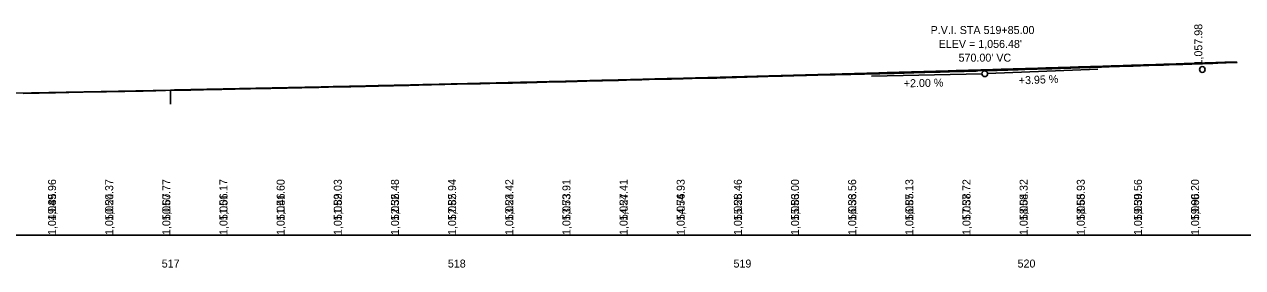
# Model space of a CAD drawing. Extents: x 2241514 to 2245530, y 509521 to 510188.
# Drawn here: x 2241926.1 to 2242352.4, y 509759.6 to 509844.8 of the extents above; entities that cross this region are included whole.
import ezdxf

# ---------------------------------------------------------------- set-up
doc = ezdxf.new("R2010")
doc.units = 0
for name, color, linetype in [('GK_Cells', 7, 'Continuous'), ('PF_P_Grade_Line', 7, 'Continuous'), ('PF_P_Sta_Elev_Text', 7, 'Continuous'), ('PF_P_Text', 7, 'Continuous'), ('PF_X_Ground_Line', 7, 'Continuous'), ('PF_X_Text', 7, 'Continuous')]:
    doc.layers.add(name, color=color, linetype=linetype)

msp = doc.modelspace()

# ---------------------------------------------------------------- linework, layer by layer
at = {"layer": 'GK_Cells'}
msp.add_line((2241529.6, 509771.03), (2245529.6, 509771.03), dxfattribs=at)
at = {"layer": 'PF_P_Grade_Line'}
msp.add_line((2241747.14, 509817.19), (2241977.14, 509821.8), dxfattribs=at)
msp.add_spline([(2241977.14, 509821.8), (2241988.54, 509822.03), (2241999.94, 509822.27), (2242011.34, 509822.51), (2242022.74, 509822.75), (2242034.14, 509823), (2242045.54, 509823.25), (2242056.94, 509823.51), (2242068.34, 509823.77), (2242079.74, 509824.04), (2242091.14, 509824.31), (2242102.54, 509824.58), (2242113.94, 509824.86), (2242125.34, 509825.15), (2242136.74, 509825.43), (2242148.14, 509825.73), (2242159.54, 509826.02), (2242170.94, 509826.33), (2242182.34, 509826.63), (2242193.74, 509826.94), (2242205.14, 509827.26), (2242216.54, 509827.58), (2242227.94, 509827.9), (2242239.34, 509828.23), (2242250.74, 509828.56), (2242262.14, 509828.9), (2242273.54, 509829.24), (2242284.94, 509829.59), (2242296.34, 509829.94), (2242307.74, 509830.29), (2242319.14, 509830.65), (2242330.54, 509831.02), (2242341.94, 509831.38), (2242350.27, 509831.66)], degree=3, dxfattribs=at)
at = {"layer": 'PF_P_Text'}
for p, q in [((2242301.71, 509829.08), (2242263.14, 509827.55)), ((2242222.55, 509826.72), (2242261.14, 509827.49)), ((2241977.14, 509816.81), (2241977.14, 509821.8))]:
    msp.add_line(p, q, dxfattribs=at)
for centre in [(2242262.14, 509827.51), (2242338.27, 509829.01)]:
    msp.add_circle(centre, 1, dxfattribs=at)
at = {"layer": 'PF_X_Ground_Line'}
for points in [[(2242179.03, 509826.36), (2242179.79, 509826.39), (2242180.04, 509826.4), (2242180.08, 509826.4), (2242180.92, 509826.43), (2242182.82, 509826.48), (2242183.42, 509826.5), (2242184.51, 509826.53), (2242184.92, 509826.54), (2242185.83, 509826.57), (2242186.23, 509826.58), (2242187.42, 509826.62), (2242188.7, 509826.65), (2242189.8, 509826.67), (2242190.28, 509826.69), (2242191.4, 509826.71), (2242192.38, 509826.73), (2242193.61, 509826.76), (2242194, 509826.77), (2242195.34, 509826.81), (2242196.54, 509826.85), (2242197.37, 509826.87), (2242199.12, 509826.93), (2242199.74, 509826.95), (2242201.9, 509827), (2242202.64, 509827.02), (2242203.05, 509827.03), (2242203.69, 509827.05), (2242205.48, 509827.09), (2242205.76, 509827.09), (2242206.18, 509827.1), (2242207.19, 509827.12), (2242208.7, 509827.16), (2242209.77, 509827.19), (2242210.78, 509827.21), (2242211.02, 509827.22), (2242211.18, 509827.22), (2242212.11, 509827.24), (2242213.73, 509827.28), (2242214.06, 509827.29), (2242214.32, 509827.29), (2242215.28, 509827.31), (2242216.32, 509827.34), (2242218.3, 509827.39), (2242219.97, 509827.43), (2242220.05, 509827.43), (2242220.12, 509827.44), (2242221.67, 509827.47), (2242223.5, 509827.51), (2242223.57, 509827.51), (2242225.28, 509827.54), (2242225.52, 509827.55), (2242225.81, 509827.55), (2242226.91, 509827.57), (2242227.52, 509827.58), (2242227.62, 509827.58), (2242227.92, 509827.59), (2242230.39, 509827.66), (2242230.39, 509827.66), (2242231.65, 509827.7), (2242233.51, 509827.77), (2242233.96, 509827.78), (2242235.52, 509827.84), (2242235.58, 509827.84), (2242236.53, 509827.87), (2242237.18, 509827.89), (2242237.42, 509827.9), (2242237.65, 509827.9), (2242239.62, 509827.97), (2242240.39, 509827.99), (2242241.2, 509828.01), (2242241.69, 509828.03), (2242242.78, 509828.06), (2242243.54, 509828.08), (2242244.23, 509828.09), (2242245.48, 509828.12), (2242246.42, 509828.13), (2242246.77, 509828.14), (2242247.24, 509828.16), (2242249.43, 509828.22), (2242249.75, 509828.23), (2242251.46, 509828.27), (2242251.81, 509828.28), (2242251.87, 509828.28), (2242253.42, 509828.32), (2242254.97, 509828.36), (2242256.09, 509828.39), (2242256.3, 509828.39), (2242256.58, 509828.4), (2242258.79, 509828.47), (2242259.07, 509828.48), (2242259.68, 509828.51), (2242262.73, 509828.61), (2242262.76, 509828.61), (2242263.63, 509828.63), (2242264.05, 509828.64), (2242266, 509828.68), (2242266.45, 509828.69), (2242268.5, 509828.76), (2242268.55, 509828.76), (2242269.62, 509828.8)], [(2242269.62, 509828.8), (2242270.19, 509828.82), (2242270.95, 509828.85), (2242271.04, 509828.85), (2242272.03, 509828.88), (2242273.62, 509828.92), (2242273.77, 509828.92), (2242274.39, 509828.95), (2242275.76, 509829.02), (2242276.11, 509829.04), (2242278.25, 509829.12), (2242279.43, 509829.15), (2242280.06, 509829.17), (2242280.26, 509829.17), (2242280.53, 509829.17), (2242281.6, 509829.2), (2242282.96, 509829.22), (2242283.41, 509829.23), (2242285.13, 509829.28), (2242285.5, 509829.29), (2242285.75, 509829.3), (2242286.31, 509829.32), (2242287.82, 509829.37), (2242288.5, 509829.4), (2242288.62, 509829.4), (2242290.16, 509829.45), (2242290.62, 509829.47), (2242292.31, 509829.53), (2242293.86, 509829.59), (2242294.32, 509829.6), (2242295.38, 509829.64), (2242296.17, 509829.66), (2242298.86, 509829.74), (2242299, 509829.74), (2242299.05, 509829.74), (2242299.99, 509829.77), (2242301.25, 509829.81), (2242303.03, 509829.87), (2242303.79, 509829.89), (2242304.13, 509829.9), (2242304.64, 509829.92), (2242305.04, 509829.94), (2242305.63, 509829.95), (2242308.23, 509830.04), (2242309.07, 509830.06), (2242309.34, 509830.07), (2242312.16, 509830.17), (2242312.34, 509830.17), (2242314.08, 509830.23), (2242314.08, 509830.23), (2242315.29, 509830.27), (2242316.22, 509830.3), (2242316.58, 509830.32), (2242318.02, 509830.37), (2242319.05, 509830.41), (2242319.54, 509830.43), (2242321.19, 509830.48), (2242321.39, 509830.49), (2242321.84, 509830.5), (2242323.48, 509830.55), (2242324.52, 509830.58), (2242324.82, 509830.59), (2242325.93, 509830.62), (2242326.25, 509830.63), (2242326.63, 509830.64), (2242328.3, 509830.7), (2242329.14, 509830.72), (2242330.26, 509830.76), (2242331.4, 509830.81), (2242332.18, 509830.84), (2242332.33, 509830.84), (2242333.52, 509830.88), (2242334.65, 509830.92), (2242336.31, 509830.97), (2242336.84, 509830.99), (2242337.53, 509831.01), (2242338.34, 509831.04), (2242340.27, 509831.1), (2242340.51, 509831.11), (2242340.85, 509831.12), (2242341.44, 509831.14), (2242341.67, 509831.15), (2242341.96, 509831.16), (2242343.16, 509831.2), (2242343.75, 509831.23), (2242345.51, 509831.29), (2242345.89, 509831.3), (2242346.65, 509831.33), (2242349.15, 509831.41), (2242349.43, 509831.42), (2242350.45, 509831.45), (2242350.45, 509831.45)], [(2242004.58, 509822.28), (2242005.18, 509822.29), (2242006.07, 509822.31), (2242007.17, 509822.34), (2242008.2, 509822.36), (2242008.6, 509822.36), (2242008.86, 509822.36), (2242009.66, 509822.36), (2242011.18, 509822.37), (2242011.92, 509822.38), (2242012.3, 509822.38), (2242014.31, 509822.43), (2242015.46, 509822.45), (2242015.77, 509822.46), (2242016.51, 509822.48), (2242017.98, 509822.51), (2242018.96, 509822.53), (2242020.49, 509822.57), (2242021.15, 509822.59), (2242022.05, 509822.61), (2242022.54, 509822.62), (2242023.12, 509822.63), (2242025.02, 509822.67), (2242025.16, 509822.67), (2242027.3, 509822.72), (2242027.75, 509822.73), (2242029.13, 509822.76), (2242029.82, 509822.78), (2242030.62, 509822.79), (2242030.96, 509822.8), (2242031.38, 509822.82), (2242032.52, 509822.85), (2242034.73, 509822.9), (2242035.22, 509822.91), (2242035.66, 509822.91), (2242037.41, 509822.93), (2242038.51, 509822.95), (2242038.73, 509822.95), (2242038.96, 509822.96), (2242040.28, 509822.98), (2242042.28, 509823.03), (2242042.8, 509823.04), (2242043.77, 509823.07), (2242044.88, 509823.1), (2242045.28, 509823.11), (2242045.92, 509823.13), (2242047.89, 509823.18), (2242049.85, 509823.22), (2242050.19, 509823.23), (2242050.55, 509823.24), (2242051.16, 509823.25), (2242052.59, 509823.29), (2242053.61, 509823.31), (2242054, 509823.32), (2242055.11, 509823.34), (2242055.42, 509823.35), (2242056.89, 509823.39), (2242057.14, 509823.39), (2242057.23, 509823.39), (2242057.75, 509823.4), (2242057.96, 509823.4), (2242059.85, 509823.43), (2242060.57, 509823.45), (2242061.69, 509823.47), (2242062.68, 509823.5), (2242062.86, 509823.51), (2242063.19, 509823.52), (2242064.05, 509823.54), (2242065.75, 509823.59), (2242065.82, 509823.59), (2242066.06, 509823.6), (2242067.21, 509823.63), (2242067.83, 509823.64), (2242068.42, 509823.65), (2242068.45, 509823.65), (2242068.49, 509823.66), (2242070.28, 509823.7), (2242071.96, 509823.75), (2242072.78, 509823.78), (2242072.99, 509823.78), (2242073.08, 509823.79), (2242073.19, 509823.79), (2242074.46, 509823.83), (2242075.41, 509823.85), (2242075.46, 509823.85), (2242075.55, 509823.86), (2242076.69, 509823.88), (2242077.5, 509823.89), (2242079.27, 509823.93), (2242080.2, 509823.95), (2242080.67, 509823.95), (2242081.75, 509823.97), (2242082.12, 509823.98), (2242082.6, 509823.98), (2242083.6, 509824), (2242084.99, 509824.03), (2242085.54, 509824.04), (2242085.61, 509824.04), (2242085.76, 509824.05), (2242088.34, 509824.11), (2242088.92, 509824.13)], [(2242088.92, 509824.13), (2242090.33, 509824.18), (2242091.31, 509824.2), (2242092.09, 509824.22), (2242092.79, 509824.23), (2242093.06, 509824.23), (2242094.85, 509824.25), (2242095.05, 509824.25), (2242095.27, 509824.26), (2242096.87, 509824.27), (2242097.43, 509824.28), (2242098.5, 509824.3), (2242100.58, 509824.34), (2242100.96, 509824.35), (2242101.93, 509824.38), (2242105.46, 509824.5), (2242106.26, 509824.53), (2242107.95, 509824.58), (2242108.84, 509824.6), (2242110.67, 509824.65), (2242111.88, 509824.67), (2242113.39, 509824.68), (2242113.8, 509824.69), (2242115.19, 509824.72), (2242115.63, 509824.73), (2242116.77, 509824.76), (2242117.19, 509824.77), (2242118.88, 509824.82), (2242119.45, 509824.84), (2242120.25, 509824.87), (2242121.81, 509824.92), (2242122.43, 509824.94), (2242122.63, 509824.95), (2242122.89, 509824.96), (2242123.69, 509824.98), (2242124.58, 509825), (2242124.89, 509825.01), (2242125.47, 509825.02), (2242127.36, 509825.06), (2242127.68, 509825.07), (2242128.42, 509825.08), (2242130.61, 509825.12), (2242131.31, 509825.14), (2242132.15, 509825.15), (2242132.78, 509825.16), (2242133.97, 509825.19), (2242135.41, 509825.23), (2242136.71, 509825.28), (2242138.61, 509825.35), (2242139.15, 509825.37), (2242139.94, 509825.38), (2242140.25, 509825.39), (2242142.01, 509825.44), (2242142.42, 509825.45), (2242142.65, 509825.46), (2242143.33, 509825.48), (2242144.75, 509825.53), (2242146.15, 509825.57), (2242147.34, 509825.59), (2242147.66, 509825.6), (2242149.46, 509825.61), (2242149.73, 509825.62), (2242150.26, 509825.62), (2242151.14, 509825.63), (2242151.51, 509825.64), (2242152.47, 509825.67), (2242153.94, 509825.7), (2242154.69, 509825.73), (2242155.61, 509825.75), (2242156.57, 509825.77), (2242157.77, 509825.82), (2242159.24, 509825.86), (2242159.57, 509825.87), (2242159.73, 509825.87), (2242162.46, 509825.94), (2242162.54, 509825.94), (2242162.92, 509825.95), (2242163.35, 509825.96), (2242163.49, 509825.97), (2242163.63, 509825.97), (2242163.83, 509825.97), (2242165.11, 509825.98), (2242165.56, 509825.99), (2242167.47, 509826), (2242167.7, 509826), (2242167.81, 509826.01), (2242167.86, 509826.01), (2242168.4, 509826.02), (2242169.83, 509826.06), (2242170.02, 509826.06), (2242170.17, 509826.06), (2242171.58, 509826.11), (2242172.92, 509826.16), (2242173.6, 509826.19), (2242174.72, 509826.24), (2242175.3, 509826.26), (2242175.78, 509826.27), (2242176.39, 509826.29), (2242177.62, 509826.32), (2242178.18, 509826.34), (2242179.03, 509826.36)], [(2241925.59, 509820.63), (2241926.5, 509820.66), (2241927.5, 509820.69), (2241927.99, 509820.7), (2241929.14, 509820.73), (2241930.61, 509820.76), (2241931.28, 509820.77), (2241932.65, 509820.79), (2241933.41, 509820.81), (2241935.13, 509820.84), (2241936.31, 509820.87), (2241936.9, 509820.88), (2241938.18, 509820.91), (2241938.58, 509820.91), (2241939.02, 509820.93), (2241941.03, 509820.98), (2241941.63, 509821), (2241942.91, 509821.03), (2241943.44, 509821.04), (2241945.64, 509821.09), (2241946.64, 509821.1), (2241948.59, 509821.13), (2241948.79, 509821.13), (2241948.99, 509821.14), (2241951.04, 509821.16), (2241951.46, 509821.17), (2241952.03, 509821.18), (2241953.72, 509821.21), (2241954.1, 509821.22), (2241954.83, 509821.23), (2241955.83, 509821.25), (2241956.43, 509821.26), (2241956.69, 509821.27), (2241957.25, 509821.28), (2241959.65, 509821.32), (2241960.59, 509821.33), (2241961.25, 509821.34), (2241964.12, 509821.37), (2241964.34, 509821.38), (2241966.11, 509821.43), (2241966.99, 509821.45), (2241967.59, 509821.47), (2241969.31, 509821.51), (2241969.67, 509821.52), (2241970.38, 509821.54), (2241972.12, 509821.59), (2241974.11, 509821.64), (2241975, 509821.66), (2241975.43, 509821.67), (2241977.58, 509821.71), (2241978.44, 509821.73), (2241979.09, 509821.74), (2241979.89, 509821.75), (2241981.8, 509821.78), (2241982.34, 509821.79), (2241982.69, 509821.8), (2241983.69, 509821.81), (2241984.31, 509821.82), (2241986.18, 509821.86), (2241987, 509821.88), (2241987.49, 509821.9), (2241988.31, 509821.92), (2241988.78, 509821.93), (2241989.39, 509821.95), (2241990.25, 509821.97), (2241991.17, 509821.98), (2241991.86, 509822), (2241993.77, 509822.03), (2241994.36, 509822.03), (2241995.21, 509822.05), (2241995.85, 509822.06), (2241996.8, 509822.08), (2241997.13, 509822.09), (2241998.99, 509822.13), (2241999.77, 509822.15), (2242001.9, 509822.2), (2242003.02, 509822.23), (2242003.05, 509822.23), (2242003.1, 509822.23), (2242004.58, 509822.28)]]:
    msp.add_lwpolyline(points, dxfattribs=at)

# ---------------------------------------------------------------- texts
at = {"layer": 'PF_P_Sta_Elev_Text'}
for s, p in [('517', (2241974.13, 509759.63)), ('518', (2242074.25, 509759.63)), ('519', (2242174.21, 509759.63)), ('520', (2242273.62, 509759.63))]:
    msp.add_text(s, height=2.8, dxfattribs=at).set_placement(p)
at = {"layer": 'PF_P_Text'}
for s, p in [('P.V.I. STA 519+85.00', (2242243.19, 509841.43)), ("ELEV = 1,056.48'", (2242246.01, 509836.56)), ("570.00' VC", (2242252.97, 509831.75))]:
    msp.add_text(s, height=2.8, dxfattribs=at).set_placement(p)
for s, rotation, p in [('1,057.98', 90, (2242338.27, 509830.41)), ('+2.00 %', 1.1485, (2242233.83, 509822.75)), ('+3.95 %', 2.262, (2242274.09, 509823.78)), ('1,049.96', 90, (2241937.14, 509776.03)), ('1,050.37', 90, (2241957.14, 509776.03)), ('1,050.77', 90, (2241977.14, 509776.03)), ('1,051.17', 90, (2241997.14, 509776.03)), ('1,051.60', 90, (2242017.14, 509776.03)), ('1,052.03', 90, (2242037.14, 509776.03)), ('1,052.48', 90, (2242057.14, 509776.03)), ('1,052.94', 90, (2242077.14, 509776.03)), ('1,053.42', 90, (2242097.14, 509776.03)), ('1,053.91', 90, (2242117.14, 509776.03)), ('1,054.41', 90, (2242137.14, 509776.03)), ('1,054.93', 90, (2242157.14, 509776.03)), ('1,055.46', 90, (2242177.14, 509776.03)), ('1,056.00', 90, (2242197.14, 509776.03)), ('1,056.56', 90, (2242217.14, 509776.03)), ('1,057.13', 90, (2242237.14, 509776.03)), ('1,057.72', 90, (2242257.14, 509776.03)), ('1,058.32', 90, (2242277.14, 509776.03)), ('1,058.93', 90, (2242297.14, 509776.03)), ('1,059.56', 90, (2242317.14, 509776.03)), ('1,060.20', 90, (2242337.14, 509776.03))]:
    msp.add_text(s, height=2.8, rotation=rotation, dxfattribs=at).set_placement(p)
at = {"layer": 'PF_X_Text'}
for s, p in [('1,049.85', (2241937.14, 509771.03)), ('1,050.24', (2241957.14, 509771.03)), ('1,050.67', (2241977.14, 509771.03)), ('1,051.06', (2241997.14, 509771.03)), ('1,051.46', (2242017.14, 509771.03)), ('1,051.89', (2242037.14, 509771.03)), ('1,052.36', (2242057.14, 509771.03)), ('1,052.85', (2242077.14, 509771.03)), ('1,053.24', (2242097.14, 509771.03)), ('1,053.73', (2242117.14, 509771.03)), ('1,054.27', (2242137.14, 509771.03)), ('1,054.76', (2242157.14, 509771.03)), ('1,055.28', (2242177.14, 509771.03)), ('1,055.83', (2242197.14, 509771.03)), ('1,056.33', (2242217.14, 509771.03)), ('1,056.85', (2242237.14, 509771.03)), ('1,057.38', (2242257.14, 509771.03)), ('1,058.04', (2242277.14, 509771.03)), ('1,058.65', (2242297.14, 509771.03)), ('1,059.30', (2242317.14, 509771.03)), ('1,059.96', (2242337.14, 509771.03))]:
    msp.add_text(s, height=2.8, rotation=90, dxfattribs=at).set_placement(p)

doc.saveas('drawing.dxf')
